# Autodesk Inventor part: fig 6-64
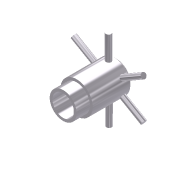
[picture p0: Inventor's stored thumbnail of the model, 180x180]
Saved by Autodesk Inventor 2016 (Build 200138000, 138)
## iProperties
Shininess: 77.0
Angle Display Precision: 2
Document Length Units: 11269
Document Angle Units: 11279
Document Time Units: 11290
Document Mass Units: 11283
Document Length Units Precision: 3
Document Angle Units Precision: 2
Compacted: True
Created: 2001-12
Part Number: fig 6-64
Document SubType Name: Modeling
Designer: Renu Muthoo
Density: 1 g/cm^3
Material: Generic
Appearance: Metal-AL-6061 (Polished)
Density: 0.0
Volumn: 0.0
Area: 0.0
PropertySet Name: Model Information
Control State: 0
Master: False
Checked Out: False
Author: Renu Muthoo
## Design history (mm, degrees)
sketch "Sketch2"
  geometry: L1 (-9.573, -4.327)-(-9.573, -5.327); L2 (-9.573, -5.327)-(-4.573, -5.327); L3 (-4.573, -5.327)-(-4.573, -6.327); L4 (-4.573, -6.327)-(9.427, -6.327); L5 (9.427, -6.327)-(10.427, -5.327); L6 (10.427, -5.327)-(10.427, -4.327); L7 (10.427, -4.327)-(-9.573, -4.327); L8 (-13.687, -0.327)-(14, -0.327)
  constraints: 16 end point, 5 parallel, 1 perpendicular, 1 vertical
  dimensions: "d9" = 20 distance of L6.end L1.start; "d10" = 5 distance of L1.end L2.end; "d11" = 12 diameter of L4 L8; "d12" = 10 diameter of L2 L8; "d13" = 8 diameter of L7 L8; "d14" = 45 deg angle of L5 L4; "d15" = 1 horizontal distance of L5.end L4.end
revolve "Revolution2" sketch "Sketch2" stored, may be unused: angle "d16" = 90 deg
workplane "Work Plane1"
workplane "Work Plane2"
sketch "Sketch3"
  geometry: L1 (-4, 8)-(4, 8) reference; C1 r 1 at (-0.098, 5)
  constraints: 1 centre point
  dimensions: "d18" = 3 distance from line of L1 C1.centre; "d19" = 2 diameter of C1
extrude "Extrusion1" join sketch "Sketch3" distance "d20" = 10; taper "d21" = 0 deg
pattern_circular "Circular Pattern3" dims angle "d29" = 360 deg
body "Solid1"
other parameters: "d17" = -1
